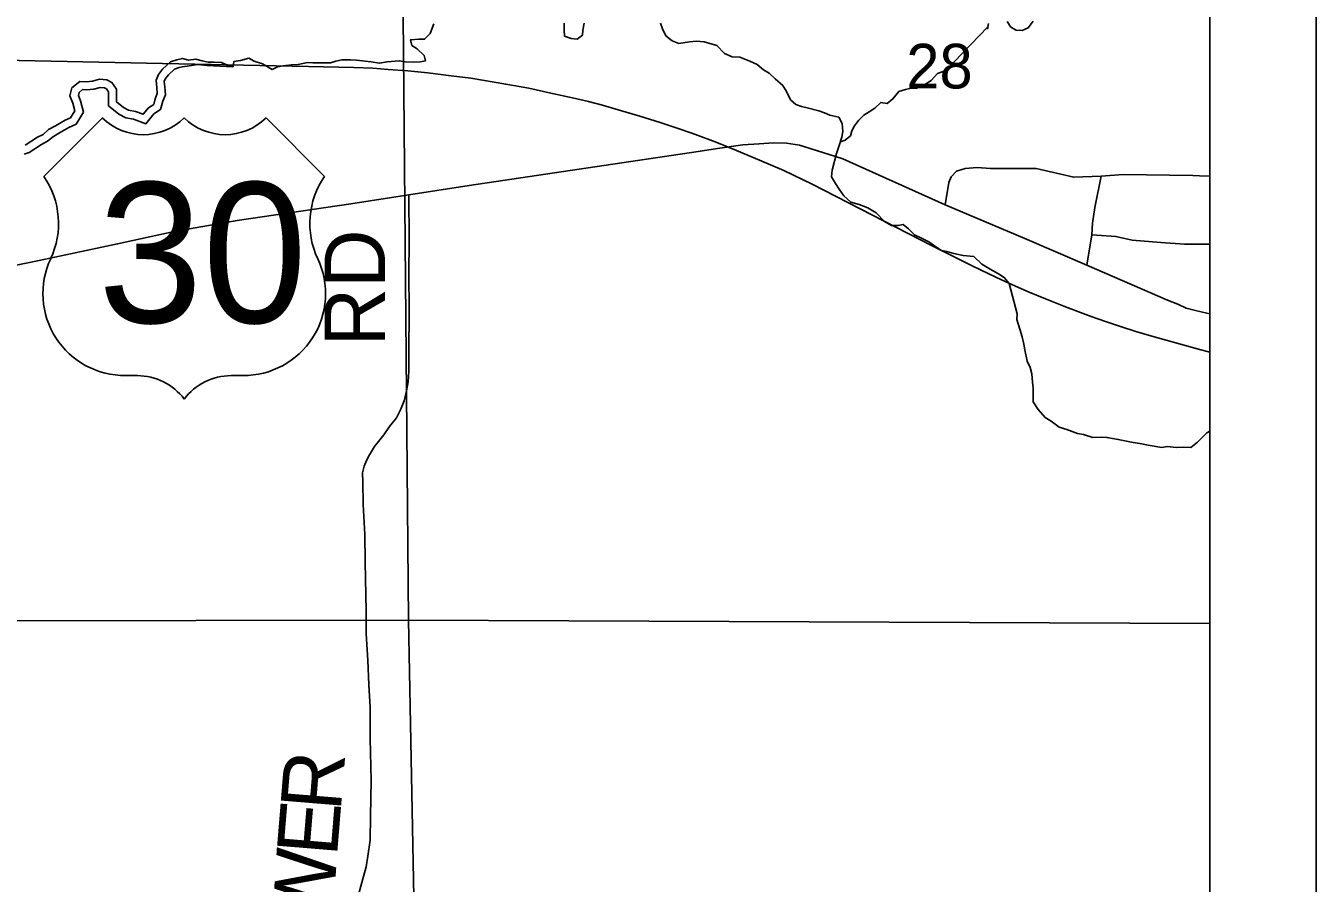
# Model space of a CAD drawing. Extents: x 0 to 34, y 0 to 22.
# Drawn here: x 7.789 to 9, y 17.784 to 18.589 of the extents above; entities that cross this region are included whole.
import ezdxf

# ---------------------------------------------------------------- set-up
doc = ezdxf.new("R2010")
doc.units = 0
for name, color, linetype in [('Default', 7, 'Continuous'), ('SH_Cut_Line', 7, 'Continuous'), ('SH_Data', 7, 'Continuous')]:
    doc.layers.add(name, color=color, linetype=linetype)

msp = doc.modelspace()

# ---------------------------------------------------------------- linework, layer by layer
at = {"layer": 'Default'}
for p, q in [((7.8604, 18.5021), (7.8054, 18.4471)), ((8.0691, 18.4471), (8.0142, 18.5021)), ((8.8903, 18.4479), (8.9, 18.4476)), ((7.8823, 18.2604), (7.8933, 18.2604)), ((7.9812, 18.2604), (7.9922, 18.2604))]:
    msp.add_line(p, q, dxfattribs=at)
for points in [[(6.2871, 17.0188), (6.3215, 17.0189), (6.3876, 17.0173), (6.6903, 17.0144), (6.927, 17.0189), (6.9328, 17.0189), (7.2045, 17.0191), (7.211, 17.0191), (8.2009, 17.0196), (8.9, 17.02), (8.9, 20.9), (6.2315, 20.9)], [(7.9831, 18.5501), (7.984, 18.555), (7.99, 18.5561), (7.998, 18.5581), (8.0029, 18.5554), (8.0109, 18.5528), (8.0197, 18.5475), (8.025, 18.5499), (8.0303, 18.551), (8.0379, 18.5518), (8.0443, 18.5522), (8.0531, 18.5542), (8.058, 18.5538), (8.0747, 18.5539), (8.0796, 18.5554), (8.0853, 18.5566), (8.0933, 18.5566), (8.099, 18.5563), (8.1127, 18.5548), (8.1206, 18.5534), (8.1278, 18.5549), (8.1392, 18.5557), (8.1446, 18.5546), (8.1521, 18.5543), (8.159, 18.5547), (8.1639, 18.5558), (8.1624, 18.5608), (8.1559, 18.5668), (8.1509, 18.5702), (8.1498, 18.5755), (8.1574, 18.5759), (8.163, 18.576), (8.1683, 18.5813), (8.1717, 18.5904)], [(8.2939, 18.591), (8.294, 18.5849), (8.2944, 18.5789), (8.3005, 18.5766), (8.3062, 18.5759), (8.3111, 18.5797), (8.3114, 18.5846), (8.3129, 18.5911)], [(8.3843, 18.5911), (8.3862, 18.5858), (8.3893, 18.579), (8.3954, 18.5744), (8.4015, 18.5718), (8.4117, 18.5734), (8.4182, 18.5742), (8.4254, 18.5734), (8.4372, 18.5701), (8.4444, 18.5625), (8.4517, 18.5595), (8.4589, 18.5592), (8.4684, 18.5554), (8.4752, 18.5521), (8.481, 18.5471), (8.4863, 18.5441), (8.492, 18.5389), (8.4993, 18.5324), (8.5027, 18.5268), (8.5065, 18.5192)], [(8.6917, 18.5875), (8.6522, 18.5465), (8.6446, 18.5438), (8.6386, 18.5373), (8.6299, 18.5316), (8.6249, 18.53), (8.6196, 18.53), (8.6143, 18.5288), (8.6082, 18.5269), (8.6026, 18.52), (8.5973, 18.5158), (8.5912, 18.5166), (8.5855, 18.5112), (8.5802, 18.5078), (8.5753, 18.5047), (8.5704, 18.4998), (8.5666, 18.4948), (8.564, 18.4899), (8.5627, 18.4854)], [(8.6913, 18.5854), (8.6924, 18.5907)], [(8.7099, 18.5927), (8.7133, 18.5874), (8.7183, 18.5844), (8.724, 18.584), (8.7296, 18.5867), (8.7342, 18.5928)], [(8.9, 18.2823), (8.8917, 18.2845), (8.8456, 18.2972), (8.8306, 18.3016), (8.8164, 18.3064), (8.8021, 18.311), (8.7886, 18.3159), (8.7761, 18.3205), (8.763, 18.3256), (8.7458, 18.3322), (8.7306, 18.3385), (8.7178, 18.3441), (8.7045, 18.3502), (8.6926, 18.3557), (8.677, 18.3632), (8.6395, 18.382), (8.5269, 18.4398), (8.5001, 18.4527), (8.4775, 18.4626), (8.4559, 18.4715), (8.4357, 18.4796), (8.4172, 18.4865), (8.4038, 18.4911), (8.3842, 18.4977), (8.3651, 18.5038), (8.3447, 18.5098), (8.3299, 18.514), (8.3168, 18.5174), (8.3018, 18.5209), (8.2814, 18.5254), (8.2608, 18.53), (8.2391, 18.5337), (8.2065, 18.5393), (8.188, 18.5417), (8.1659, 18.5443), (8.1472, 18.5462), (8.1288, 18.5476), (8.1142, 18.5488), (8.0964, 18.5495), (8.054, 18.5505), (7.9168, 18.5533), (7.8123, 18.5555), (7.6771, 18.5582)], [(7.787, 18.468), (7.7916, 18.4698), (7.8032, 18.4773), (7.809, 18.4802), (7.8144, 18.4848), (7.8202, 18.488), (7.8291, 18.4932), (7.8357, 18.4963), (7.8428, 18.5074), (7.8399, 18.5183), (7.8379, 18.5233), (7.8386, 18.526), (7.8419, 18.5287), (7.8451, 18.5285), (7.8525, 18.529), (7.8583, 18.5307), (7.8624, 18.5303), (7.8643, 18.5294), (7.8661, 18.5267), (7.8661, 18.5136), (7.8759, 18.5056), (7.8826, 18.5021), (7.8896, 18.5009), (7.9013, 18.4966), (7.9088, 18.5059), (7.9151, 18.5099), (7.9173, 18.5177), (7.9197, 18.5239), (7.9191, 18.5314), (7.9185, 18.5364), (7.9196, 18.539), (7.9224, 18.5427), (7.9282, 18.548), (7.9324, 18.5493), (7.9355, 18.55)], [(7.9831, 18.5501), (7.9771, 18.5519), (7.9722, 18.5541), (7.9654, 18.5545), (7.9597, 18.5545), (7.954, 18.5556), (7.9483, 18.5571), (7.9414, 18.5563), (7.9357, 18.5578), (7.9304, 18.5566), (7.9244, 18.5547), (7.9168, 18.5478), (7.913, 18.5429), (7.9108, 18.5375), (7.9116, 18.5307), (7.912, 18.525), (7.9101, 18.5201), (7.9086, 18.5148), (7.9037, 18.5117), (7.8988, 18.5056), (7.8916, 18.5082), (7.8851, 18.5093), (7.8802, 18.512), (7.8737, 18.5172), (7.8736, 18.529), (7.8694, 18.5354), (7.8645, 18.5377), (7.8576, 18.5384), (7.8512, 18.5365), (7.8451, 18.5361), (7.8394, 18.5364), (7.8318, 18.5303), (7.83, 18.5227), (7.8327, 18.5159), (7.8346, 18.5087), (7.8305, 18.5022), (7.8256, 18.4999), (7.8165, 18.4946), (7.81, 18.4911), (7.8047, 18.4865), (7.7994, 18.4839), (7.7881, 18.4766)], [(7.9355, 18.55), (7.9421, 18.5511), (7.9496, 18.5521), (7.9588, 18.5513), (7.9708, 18.5508), (7.9831, 18.5501)], [(8.5065, 18.5192), (8.5115, 18.5147), (8.5168, 18.5128), (8.5221, 18.5117), (8.5332, 18.5087), (8.5385, 18.5068), (8.5434, 18.5046), (8.5518, 18.5027), (8.5549, 18.497), (8.5557, 18.4895), (8.5546, 18.4841), (8.5519, 18.4754), (8.5497, 18.4686), (8.5456, 18.453), (8.5449, 18.4469), (8.5487, 18.4405), (8.5521, 18.4352), (8.5564, 18.4291), (8.5632, 18.4231), (8.5708, 18.4208), (8.5792, 18.4178), (8.5868, 18.413), (8.5948, 18.405), (8.6013, 18.4013), (8.6074, 18.4013), (8.6123, 18.4021), (8.6173, 18.3979), (8.623, 18.3923), (8.6302, 18.3889), (8.6363, 18.3859), (8.6428, 18.381), (8.6481, 18.3776), (8.6531, 18.3768), (8.6599, 18.375), (8.6686, 18.3731), (8.6785, 18.372), (8.6861, 18.3649), (8.6938, 18.3603), (8.7018, 18.3558), (8.7071, 18.3524), (8.7117, 18.3468), (8.7194, 18.3183), (8.7191, 18.313), (8.7218, 18.3039), (8.7241, 18.2967), (8.7256, 18.2899), (8.7264, 18.2846), (8.7288, 18.274), (8.7314, 18.2679), (8.733, 18.2619), (8.7338, 18.2543), (8.7342, 18.2486), (8.7343, 18.2357), (8.7389, 18.2285), (8.7457, 18.221), (8.7511, 18.2176), (8.7587, 18.2119), (8.7659, 18.2097), (8.7758, 18.2059), (8.7815, 18.2052), (8.7902, 18.2022), (8.7986, 18.2026), (8.8035, 18.2023), (8.8142, 18.2004), (8.8282, 18.1974), (8.8343, 18.1967), (8.8423, 18.1949), (8.8552, 18.193), (8.8601, 18.1938), (8.8685, 18.1927), (8.875, 18.1931), (8.8822, 18.1928), (8.8886, 18.1977), (8.8973, 18.2065), (8.9, 18.2083)], [(8.4198, 18.4707), (8.4378, 18.4734), (8.4618, 18.4768), (8.4772, 18.4777), (8.4906, 18.4786), (8.5028, 18.4783), (8.515, 18.4765), (8.531, 18.4716), (8.5556, 18.4637), (8.6516, 18.4206), (8.7266, 18.3891), (8.7847, 18.3639), (8.8603, 18.331), (8.87, 18.3273), (8.8778, 18.3237), (8.8867, 18.3213), (8.8974, 18.3189), (8.9, 18.3184)], [(8.5627, 18.4854), (8.5578, 18.4812), (8.5533, 18.4796)], [(7.5949, 18.3248), (7.6124, 18.3285), (7.6907, 18.3457), (7.801, 18.3684), (7.8747, 18.3839), (7.9278, 18.3955), (7.9869, 18.4058), (8.0938, 18.4215), (8.1482, 18.4299), (8.2048, 18.4387), (8.4198, 18.4707)], [(8.6516, 18.4206), (8.655, 18.4414), (8.6573, 18.4469), (8.6624, 18.452), (8.6704, 18.4547), (8.6818, 18.4555), (8.6942, 18.4546), (8.7371, 18.4548), (8.7724, 18.4464), (8.7981, 18.4476)], [(8.7847, 18.3639), (8.7893, 18.3924), (8.7901, 18.4033), (8.7921, 18.4179), (8.7981, 18.4476)], [(8.7981, 18.4476), (8.8187, 18.4491), (8.8843, 18.448), (8.8903, 18.4479)], [(8.1081, 18.0181), (8.108, 18.0191), (8.108, 18.0392), (8.1072, 18.0854), (8.1067, 18.1111), (8.1052, 18.1394), (8.1049, 18.1606), (8.1048, 18.1692), (8.1062, 18.1753), (8.1084, 18.1805), (8.1111, 18.186), (8.1158, 18.1937), (8.1246, 18.2046), (8.1301, 18.2125), (8.1365, 18.2206), (8.1404, 18.2281), (8.1438, 18.2365), (8.1461, 18.2459), (8.1474, 18.2546), (8.1482, 18.2645), (8.1481, 18.2809), (8.1485, 18.322), (8.1482, 18.3558), (8.1485, 18.3868), (8.1482, 18.4299)], [(8.7893, 18.3924), (8.8119, 18.3909), (8.8272, 18.3875), (8.854, 18.3852), (8.8765, 18.3835), (8.9, 18.3835)], [(8.0998, 17.7695), (8.1039, 17.7845), (8.1082, 17.7995), (8.1098, 17.8095), (8.1117, 17.8243), (8.1121, 17.847), (8.1128, 17.8804), (8.112, 17.9198), (8.1118, 17.9491), (8.1106, 17.97), (8.1097, 17.9932), (8.1081, 18.0181)]]:
    msp.add_lwpolyline(points, dxfattribs=at)
for points in [[(7.1411, 19.0266), (8.1392, 19.0236), (8.1478, 18.0308), (7.1486, 18.0293)], [(8.9, 18.0277), (8.9, 19.0311), (8.1392, 19.0236), (8.1478, 18.0308)], [(7.1486, 18.0293), (8.1478, 18.0308), (8.1673, 17.0247), (7.2555, 17.0252), (7.1604, 17.0251)], [(8.9, 17.0255), (8.9, 18.0277), (8.1478, 18.0308), (8.1673, 17.0247), (8.2594, 17.0247)]]:
    msp.add_lwpolyline(points, close=True, dxfattribs=at)
for centre, radius, start, end in [((7.8988, 18.5413), 0.0549, 225.573, 314.427), ((7.9757, 18.5413), 0.0549, 225.573, 314.427), ((7.7424, 18.403), 0.0769, 334.5471, 35.0009), ((8.1321, 18.403), 0.0769, 144.9991, 205.4529), ((7.8815, 18.3373), 0.0769, 154.8319, 270.6383), ((7.9931, 18.3373), 0.0769, 269.3617, 25.1681), ((7.8933, 18.2054), 0.0549, 36.8699, 90), ((7.9812, 18.2054), 0.0549, 90, 143.1301)]:
    msp.add_arc(centre, radius, start, end, dxfattribs=at)
at = {"layer": 'SH_Cut_Line'}
msp.add_lwpolyline([(6.2871, 17.0188), (6.3215, 17.0189), (6.3876, 17.0173), (6.6903, 17.0144), (6.927, 17.0189), (6.9328, 17.0189), (7.2045, 17.0191), (7.211, 17.0191), (8.2009, 17.0196), (8.9, 17.02), (8.9, 20.9), (6.2315, 20.9)], dxfattribs=at)
at = {"layer": 'SH_Data'}
for p, q in [((9, 21), (9, 14)), ((8.9, 20.9), (8.9, 14.1))]:
    msp.add_line(p, q, dxfattribs=at)

# ---------------------------------------------------------------- texts
at = {"layer": 'Default'}
for s, height, rotation, p in [('28', 0.04186, 0, (8.6152, 18.5298)), ('RD', 0.05682, 90, (8.1258, 18.2877)), ('30', 0.000189, 0, (7.8981, 18.3355)), ('R', 0.0568, 85.32, (8.0841, 17.8507)), ('E', 0.0568, 85.289, (8.0806, 17.8083)), ('W', 0.0568, 86.243, (8.0763, 17.7428))]:
    msp.add_text(s, height=height, rotation=rotation, dxfattribs=at).set_placement(p)
for s, height, p in [('30', 0.13184, (7.8564, 18.3098)), ('0', 0.000189, (7.9372, 18.3747)), ('/', 0.000189, (7.9372, 18.3747))]:
    msp.add_text(s, height=height, dxfattribs=at).set_placement(p)

doc.saveas('drawing.dxf')
